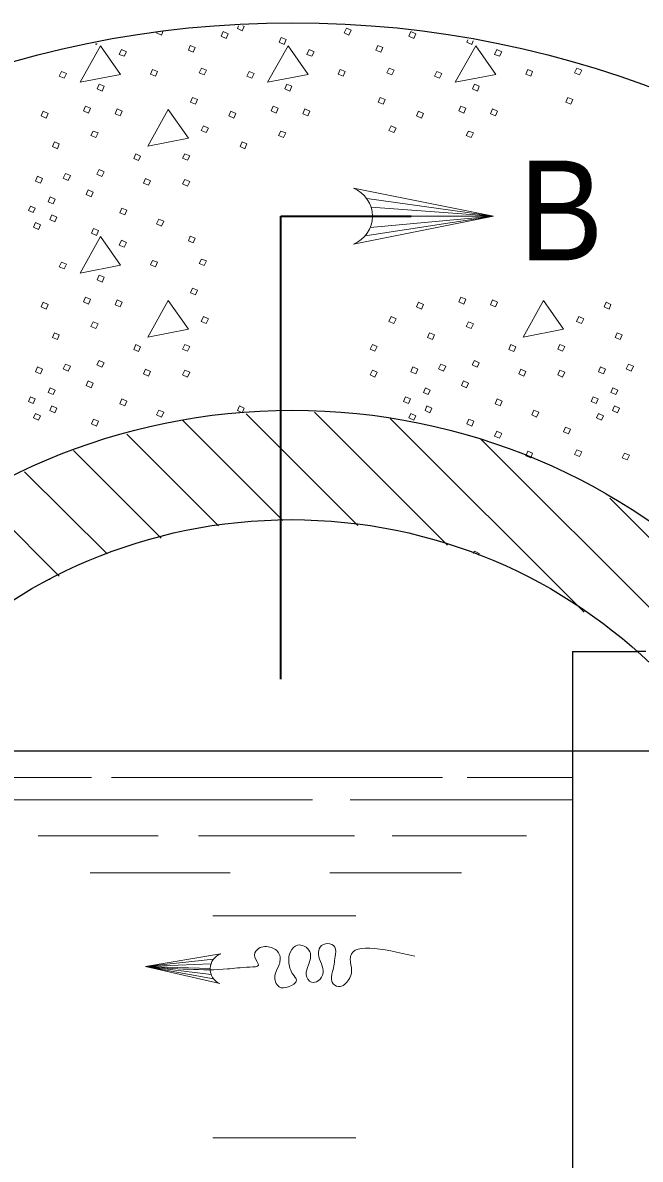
# Model space of a CAD drawing. Extents: x 1083.1 to 1117.1, y 719.4 to 741.4.
# Drawn here: x 1090.324 to 1091.808, y 735.057 to 737.789 of the extents above; entities that cross this region are included whole.
import ezdxf
from ezdxf.enums import TextEntityAlignment as Align

# ---------------------------------------------------------------- set-up
doc = ezdxf.new("R2010")
doc.units = 0
doc.header["$LTSCALE"] = 0.062
doc.linetypes.add('LONG_DASHED', pattern=[7.5, 6, -1.5])
doc.layers.add('1', color=7, linetype='Continuous', lineweight=13)

msp = doc.modelspace()

# ---------------------------------------------------------------- linework, layer by layer
at = {"layer": '1'}
for p, q in [((1091.15075, 737.36683), (1091.45517, 737.32425)), ((1091.16108, 737.34575), (1091.45517, 737.32425)), ((1091.14717, 737.27717), (1091.45517, 737.32425)), ((1091.15883, 737.29692), (1091.45517, 737.32425)), ((1091.16417, 737.32425), (1091.45517, 737.32425)), ((1090.94925, 736.59283), (1090.70783, 736.83417)), ((1091.12925, 736.58067), (1090.86067, 736.84933)), ((1091.3445, 736.53325), (1091.02483, 736.85292)), ((1091.67367, 736.372), (1091.20733, 736.83833)), ((1090.7945, 736.57975), (1090.57408, 736.80008)), ((1092.4165, 735.79717), (1091.425, 736.78842)), ((1090.65617, 736.55025), (1090.4455, 736.76075)), ((1090.52633, 736.51225), (1090.32833, 736.71008)), ((1090.4115, 736.45917), (1090.2175, 736.65317)), ((1092.27733, 736.10408), (1091.73483, 736.64642)), ((1091.40675, 736.51342), (1091.4095, 736.51883)), ((1090.38842, 736.45033), (1090.3895, 736.45317)), ((1090.3895, 736.45317), (1090.3915, 736.45217)), ((1090.24283, 735.97483), (1090.48883, 735.97483)), ((1090.53692, 735.97483), (1091.33317, 735.97483)), ((1091.39225, 735.97483), (1091.64517, 735.97483)), ((1090.28625, 735.92117), (1091.02067, 735.92117)), ((1091.11092, 735.92117), (1091.64517, 735.92117)), ((1090.36083, 735.83458), (1090.64908, 735.83458)), ((1090.74625, 735.83458), (1091.12133, 735.83458)), ((1091.21167, 735.83458), (1091.53458, 735.83458)), ((1090.48583, 735.74558), (1090.82275, 735.74558)), ((1091.06233, 735.74558), (1091.37825, 735.74558)), ((1090.781, 735.64233), (1091.12483, 735.64233)), ((1090.78225, 735.53842), (1090.619, 735.52075)), ((1090.77625, 735.52725), (1090.619, 735.52075)), ((1090.77433, 735.51583), (1090.619, 735.52075)), ((1090.77675, 735.50117), (1090.619, 735.52075)), ((1090.7825, 735.4905), (1090.619, 735.52075)), ((1090.781, 735.10858), (1091.12483, 735.10858))]:
    msp.add_line(p, q, dxfattribs=at)
at = {"layer": '1', "lineweight": 35}
for p, q in [((1090.944, 737.32425), (1091.25742, 737.32425)), ((1090.944, 736.21142), (1090.944, 737.32425))]:
    msp.add_line(p, q, dxfattribs=at)
at = {"layer": '1', "lineweight": 25}
for p, q in [((1091.64517, 736.2775), (1091.64517, 734.37467)), ((1091.64517, 736.2775), (1091.80183, 736.2775)), ((1090.24283, 736.03933), (1091.64517, 736.03933))]:
    msp.add_line(p, q, dxfattribs=at)
at = {"layer": '1', "linetype": 'LONG_DASHED', "lineweight": 25}
for p, q in [((1093.23775, 736.2775), (1091.80183, 736.2775)), ((1091.64517, 736.03933), (1095.35325, 736.03933))]:
    msp.add_line(p, q, dxfattribs=at)
at = {"layer": '1'}
for points in [[(1090.66167, 737.76967), (1090.65692, 737.75942), (1090.64508, 737.765), (1090.64592, 737.76675)], [(1090.85283, 737.78242), (1090.85633, 737.78075), (1090.85158, 737.76975), (1090.83975, 737.77525), (1090.8425, 737.78175)], [(1090.50183, 737.73933), (1090.50108, 737.73725), (1090.49825, 737.73858)], [(1091.40667, 737.74625), (1091.40317, 737.73725), (1091.39125, 737.74283), (1091.39375, 737.7485)], [(1091.11892, 737.257), (1091.45517, 737.32425), (1091.11892, 737.3915)], [(1091.4095, 736.51883), (1091.42133, 736.51325), (1091.41942, 736.5095)], [(1090.79733, 735.47925), (1090.619, 735.52075), (1090.7995, 735.55108)]]:
    msp.add_lwpolyline(points, dxfattribs=at)
for points in [[(1090.80575, 737.76817), (1090.81758, 737.76258), (1090.81283, 737.7515), (1090.801, 737.75708)], [(1091.10167, 737.77608), (1091.1135, 737.77133), (1091.108, 737.75942), (1091.09608, 737.765)], [(1091.25675, 737.76817), (1091.26858, 737.76258), (1091.26383, 737.7515), (1091.252, 737.75708)], [(1090.945, 737.75392), (1090.95683, 737.74917), (1090.95208, 737.73725), (1090.94025, 737.74283)], [(1090.51058, 737.73408), (1090.4615, 737.64625), (1090.55883, 737.66525)], [(1090.56117, 737.72542), (1090.57308, 737.71983), (1090.5675, 737.70875), (1090.55567, 737.7135)], [(1090.72658, 737.73492), (1090.73842, 737.73017), (1090.73367, 737.71908), (1090.72183, 737.72383)], [(1090.96158, 737.73408), (1090.9125, 737.64625), (1091.00983, 737.66525)], [(1091.01225, 737.72542), (1091.02408, 737.71983), (1091.01858, 737.70875), (1091.00667, 737.7135)], [(1091.17758, 737.73492), (1091.1895, 737.73017), (1091.18475, 737.71908), (1091.17283, 737.72383)], [(1091.41267, 737.73408), (1091.36358, 737.64625), (1091.46092, 737.66525)], [(1091.46325, 737.72542), (1091.47517, 737.71983), (1091.46958, 737.70875), (1091.45775, 737.7135)], [(1090.41717, 737.67242), (1090.42908, 737.66767), (1090.4235, 737.65658), (1090.41167, 737.66133)], [(1090.63558, 737.67717), (1090.64742, 737.67242), (1090.64267, 737.66133), (1090.63083, 737.66608)], [(1090.7535, 737.68033), (1090.76533, 737.67558), (1090.75983, 737.6645), (1090.74792, 737.66925)], [(1090.86825, 737.67242), (1090.88008, 737.66767), (1090.87458, 737.65658), (1090.86267, 737.66133)], [(1091.08658, 737.67717), (1091.0985, 737.67242), (1091.09375, 737.66133), (1091.08183, 737.66608)], [(1091.2045, 737.68033), (1091.21642, 737.67558), (1091.21083, 737.6645), (1091.199, 737.66925)], [(1091.31925, 737.67242), (1091.33117, 737.66767), (1091.32558, 737.65658), (1091.31375, 737.66133)], [(1091.53767, 737.67717), (1091.5495, 737.67242), (1091.54475, 737.66133), (1091.53292, 737.66608)], [(1091.65558, 737.68033), (1091.66742, 737.67558), (1091.66192, 737.6645), (1091.65, 737.66925)], [(1090.50742, 737.6415), (1090.51925, 737.63675), (1090.5145, 737.62492), (1090.50267, 737.6305)], [(1090.95842, 737.6415), (1090.97033, 737.63675), (1090.96558, 737.62492), (1090.95367, 737.6305)], [(1091.4095, 737.6415), (1091.42133, 737.63675), (1091.41658, 737.62492), (1091.40475, 737.6305)], [(1090.73208, 737.60992), (1090.744, 737.60517), (1090.73925, 737.59408), (1090.72733, 737.59883)], [(1091.18317, 737.60992), (1091.195, 737.60517), (1091.19025, 737.59408), (1091.17842, 737.59883)], [(1091.63417, 737.60992), (1091.64608, 737.60517), (1091.64133, 737.59408), (1091.62942, 737.59883)], [(1090.37292, 737.57667), (1090.38475, 737.57108), (1090.38, 737.56008), (1090.36808, 737.56558)], [(1090.47492, 737.5885), (1090.48683, 737.58375), (1090.48208, 737.57192), (1090.47017, 737.57742)], [(1090.55092, 737.58217), (1090.56275, 737.57667), (1090.558, 737.56558), (1090.54617, 737.57033)], [(1090.67358, 737.58058), (1090.6245, 737.49275), (1090.72183, 737.51175)], [(1090.82392, 737.57667), (1090.83575, 737.57108), (1090.831, 737.56008), (1090.81917, 737.56558)], [(1090.926, 737.5885), (1090.93783, 737.58375), (1090.93308, 737.57192), (1090.92125, 737.57742)], [(1091.00192, 737.58217), (1091.01383, 737.57667), (1091.00908, 737.56558), (1090.99717, 737.57033)], [(1091.27492, 737.57667), (1091.28683, 737.57108), (1091.28208, 737.56008), (1091.27017, 737.56558)], [(1091.377, 737.5885), (1091.38892, 737.58375), (1091.38417, 737.57192), (1091.37225, 737.57742)], [(1091.453, 737.58217), (1091.46483, 737.57667), (1091.46008, 737.56558), (1091.44825, 737.57033)], [(1090.49317, 737.52917), (1090.505, 737.52442), (1090.4995, 737.51333), (1090.48758, 737.51808)], [(1090.75825, 737.54183), (1090.77008, 737.53633), (1090.76458, 737.52525), (1090.75267, 737.53)], [(1090.94417, 737.52917), (1090.95608, 737.52442), (1090.9505, 737.51333), (1090.93867, 737.51808)], [(1091.20925, 737.54183), (1091.22117, 737.53633), (1091.21558, 737.52525), (1091.20375, 737.53)], [(1091.39525, 737.52917), (1091.40708, 737.52442), (1091.40158, 737.51333), (1091.38967, 737.51808)], [(1090.39975, 737.50308), (1090.41167, 737.49833), (1090.40692, 737.4865), (1090.395, 737.492)], [(1090.85083, 737.50308), (1090.86267, 737.49833), (1090.85792, 737.4865), (1090.84608, 737.492)], [(1090.59525, 737.47458), (1090.60708, 737.46908), (1090.60233, 737.458), (1090.5905, 737.46275)], [(1090.71317, 737.47458), (1090.725, 737.46983), (1090.7195, 737.45875), (1090.70758, 737.4635)], [(1090.50742, 737.43658), (1090.51925, 737.43108), (1090.51375, 737.42), (1090.50183, 737.4255)], [(1090.35942, 737.42075), (1090.37125, 737.41525), (1090.36658, 737.40417), (1090.35467, 737.40892)], [(1090.42667, 737.42708), (1090.43858, 737.42233), (1090.433, 737.4105), (1090.42117, 737.41608)], [(1090.619, 737.41525), (1090.63083, 737.40975), (1090.62608, 737.39867), (1090.61425, 737.40417)], [(1090.71317, 737.41292), (1090.725, 737.40817), (1090.7195, 737.39625), (1090.70758, 737.40183)], [(1090.48125, 737.38758), (1090.49317, 737.382), (1090.48842, 737.37092), (1090.4765, 737.3765)], [(1090.3895, 737.37092), (1090.40133, 737.36542), (1090.39658, 737.35433), (1090.38475, 737.35908)], [(1090.342, 737.34875), (1090.35392, 737.344), (1090.34917, 737.333), (1090.33725, 737.33775)], [(1090.39342, 737.32742), (1090.40533, 737.32192), (1090.40058, 737.31083), (1090.38867, 737.31633)], [(1090.562, 737.344), (1090.57383, 737.3385), (1090.56908, 737.32742), (1090.55725, 737.33217)], [(1090.35467, 737.30925), (1090.36658, 737.30367), (1090.36183, 737.29258), (1090.34992, 737.29817)], [(1090.65058, 737.31717), (1090.6625, 737.31242), (1090.65692, 737.3005), (1090.64508, 737.30608)], [(1090.51058, 737.27517), (1090.4615, 737.18742), (1090.55883, 737.20633)], [(1090.49392, 737.295), (1090.50583, 737.29025), (1090.50108, 737.27833), (1090.48917, 737.28392)], [(1090.72658, 737.276), (1090.73842, 737.27125), (1090.73367, 737.26017), (1090.72183, 737.26492)], [(1090.56117, 737.2665), (1090.57308, 737.261), (1090.5675, 737.24992), (1090.55567, 737.25467)], [(1090.63558, 737.21825), (1090.64742, 737.2135), (1090.64267, 737.20242), (1090.63083, 737.20717)], [(1090.7535, 737.22142), (1090.76533, 737.21667), (1090.75983, 737.20558), (1090.74792, 737.21033)], [(1090.41717, 737.2135), (1090.42908, 737.20875), (1090.4235, 737.19767), (1090.41167, 737.20242)], [(1090.50742, 737.18267), (1090.51925, 737.17792), (1090.5145, 737.166), (1090.50267, 737.17158)], [(1090.73208, 737.151), (1090.744, 737.14625), (1090.73925, 737.13517), (1090.72733, 737.13992)], [(1090.37292, 737.11775), (1090.38475, 737.11225), (1090.38, 737.10117), (1090.36808, 737.10667)], [(1090.47492, 737.12958), (1090.48683, 737.12492), (1090.48208, 737.113), (1090.47017, 737.11858)], [(1090.55092, 737.12333), (1090.56275, 737.11775), (1090.558, 737.10667), (1090.54617, 737.11142)], [(1090.67358, 737.12175), (1090.6245, 737.03392), (1090.72183, 737.05283)], [(1091.27492, 737.11775), (1091.28683, 737.11225), (1091.28208, 737.10117), (1091.27017, 737.10667)], [(1091.377, 737.12958), (1091.38892, 737.12492), (1091.38417, 737.113), (1091.37225, 737.11858)], [(1091.453, 737.12333), (1091.46483, 737.11775), (1091.46008, 737.10667), (1091.44825, 737.11142)], [(1091.57567, 737.12175), (1091.52658, 737.03392), (1091.62392, 737.05283)], [(1091.726, 737.11775), (1091.73783, 737.11225), (1091.73308, 737.10117), (1091.72125, 737.10667)], [(1090.75825, 737.08292), (1090.77008, 737.07742), (1090.76458, 737.06633), (1090.75267, 737.07108)], [(1091.20925, 737.08292), (1091.22117, 737.07742), (1091.21558, 737.06633), (1091.20375, 737.07108)], [(1091.66033, 737.08292), (1091.67217, 737.07742), (1091.66667, 737.06633), (1091.65475, 737.07108)], [(1090.49317, 737.07025), (1090.505, 737.0655), (1090.4995, 737.05442), (1090.48758, 737.05917)], [(1091.39525, 737.07025), (1091.40708, 737.0655), (1091.40158, 737.05442), (1091.38967, 737.05917)], [(1090.39975, 737.04417), (1090.41167, 737.03942), (1090.40692, 737.02758), (1090.395, 737.03308)], [(1091.30183, 737.04417), (1091.31375, 737.03942), (1091.309, 737.02758), (1091.29708, 737.03308)], [(1091.75292, 737.04417), (1091.76475, 737.03942), (1091.76, 737.02758), (1091.74817, 737.03308)], [(1090.59525, 737.01567), (1090.60708, 737.01017), (1090.60233, 736.99908), (1090.5905, 737.00383)], [(1090.71317, 737.01567), (1090.725, 737.01092), (1090.7195, 736.99983), (1090.70758, 737.00458)], [(1091.16417, 737.01567), (1091.176, 737.01092), (1091.1705, 736.99983), (1091.15867, 737.00458)], [(1091.49733, 737.01567), (1091.50917, 737.01017), (1091.50442, 736.99908), (1091.49258, 737.00383)], [(1091.61517, 737.01567), (1091.62708, 737.01092), (1091.6215, 736.99983), (1091.60967, 737.00458)], [(1090.50742, 736.97775), (1090.51925, 736.97217), (1090.51375, 736.96108), (1090.50183, 736.96667)], [(1091.4095, 736.97775), (1091.42133, 736.97217), (1091.41583, 736.96108), (1091.40392, 736.96667)], [(1090.35942, 736.96192), (1090.37125, 736.95633), (1090.36658, 736.94525), (1090.35467, 736.95)], [(1090.42667, 736.96825), (1090.43858, 736.9635), (1090.433, 736.95158), (1090.42117, 736.95717)], [(1090.619, 736.95633), (1090.63083, 736.95083), (1090.62608, 736.93975), (1090.61425, 736.94525)], [(1090.71317, 736.954), (1090.725, 736.94925), (1090.7195, 736.93733), (1090.70758, 736.94292)], [(1091.16417, 736.954), (1091.176, 736.94925), (1091.1705, 736.93733), (1091.15867, 736.94292)], [(1091.2615, 736.96192), (1091.27333, 736.95633), (1091.26858, 736.94525), (1091.25675, 736.95)], [(1091.32875, 736.96825), (1091.34067, 736.9635), (1091.33508, 736.95158), (1091.32325, 736.95717)], [(1091.521, 736.95633), (1091.53292, 736.95083), (1091.52817, 736.93975), (1091.51633, 736.94525)], [(1091.61517, 736.954), (1091.62708, 736.94925), (1091.6215, 736.93733), (1091.60967, 736.94292)], [(1091.7125, 736.96192), (1091.72442, 736.95633), (1091.71967, 736.94525), (1091.70775, 736.95)], [(1091.77983, 736.96825), (1091.79167, 736.9635), (1091.78608, 736.95158), (1091.77425, 736.95717)], [(1090.48125, 736.92867), (1090.49317, 736.92308), (1090.48842, 736.91208), (1090.4765, 736.91758)], [(1091.38333, 736.92867), (1091.39525, 736.92308), (1091.3905, 736.91208), (1091.37858, 736.91758)], [(1090.342, 736.88992), (1090.35392, 736.88517), (1090.34917, 736.87408), (1090.33725, 736.87883)], [(1090.3895, 736.91208), (1090.40133, 736.9065), (1090.39658, 736.89542), (1090.38475, 736.90017)], [(1091.24408, 736.88992), (1091.25592, 736.88517), (1091.25125, 736.87408), (1091.23933, 736.87883)], [(1091.29158, 736.91208), (1091.30342, 736.9065), (1091.29867, 736.89542), (1091.28683, 736.90017)], [(1091.69517, 736.88992), (1091.707, 736.88517), (1091.70225, 736.87408), (1091.69042, 736.87883)], [(1091.74258, 736.91208), (1091.7545, 736.9065), (1091.74975, 736.89542), (1091.73783, 736.90017)], [(1090.39342, 736.8685), (1090.40533, 736.863), (1090.40058, 736.85192), (1090.38867, 736.85742)], [(1090.562, 736.88517), (1090.57383, 736.87958), (1090.56908, 736.8685), (1090.55725, 736.87325)], [(1090.8445, 736.8685), (1090.85633, 736.863), (1090.85158, 736.85192), (1090.83975, 736.85742)], [(1091.2955, 736.8685), (1091.30742, 736.863), (1091.30267, 736.85192), (1091.29075, 736.85742)], [(1091.46408, 736.88517), (1091.47592, 736.87958), (1091.47117, 736.8685), (1091.45933, 736.87325)], [(1091.74658, 736.8685), (1091.75842, 736.863), (1091.75367, 736.85192), (1091.74183, 736.85742)], [(1090.35467, 736.85033), (1090.36658, 736.84475), (1090.36183, 736.83375), (1090.34992, 736.83925)], [(1090.49392, 736.83608), (1090.50583, 736.83133), (1090.50108, 736.8195), (1090.48917, 736.825)], [(1090.65058, 736.85825), (1090.6625, 736.8535), (1090.65692, 736.84158), (1090.64508, 736.84717)], [(1091.25675, 736.85033), (1091.26858, 736.84475), (1091.26383, 736.83375), (1091.252, 736.83925)], [(1091.396, 736.83608), (1091.40792, 736.83133), (1091.40317, 736.8195), (1091.39125, 736.825)], [(1091.55267, 736.85825), (1091.56458, 736.8535), (1091.559, 736.84158), (1091.54717, 736.84717)], [(1091.70775, 736.85033), (1091.71967, 736.84475), (1091.71492, 736.83375), (1091.703, 736.83925)], [(1091.46325, 736.80758), (1091.47517, 736.80208), (1091.46958, 736.791), (1091.45775, 736.79575)], [(1091.62867, 736.81708), (1091.6405, 736.81233), (1091.63575, 736.80125), (1091.62392, 736.806)], [(1091.53767, 736.75933), (1091.5495, 736.75458), (1091.54475, 736.7435), (1091.53292, 736.74825)], [(1091.65558, 736.7625), (1091.66742, 736.75775), (1091.66192, 736.74667), (1091.65, 736.75142)], [(1091.77033, 736.75458), (1091.78217, 736.74983), (1091.77667, 736.73875), (1091.76475, 736.7435)]]:
    msp.add_lwpolyline(points, close=True, dxfattribs=at)
msp.add_arc((1091.09174, 737.32434), 0.07258, 292.08605, 67.91218, dxfattribs=at)
at = {"layer": '1', "lineweight": 25}
for centre, major_axis in [((1090.97275, 735.33737), (2.45238, 0)), ((1090.9718, 735.34212), (1.5159, 0)), ((1090.96895, 735.34307), (1.25185, 0))]:
    msp.add_ellipse(centre, major_axis=major_axis, ratio=0.999895, dxfattribs=at)
at = {"layer": '1'}
msp.add_ellipse((1090.81299, 735.51469), major_axis=(-0.03875, 0), ratio=0.999895, start_param=5.0665441, end_param=7.4371572, dxfattribs=at)
msp.add_spline([(1091.26633, 735.54525), (1091.11108, 735.5365), (1091.11408, 735.505), (1091.10783, 735.48925), (1091.08292, 735.47242), (1091.0675, 735.48267), (1091.06858, 735.5085), (1091.07492, 735.54442), (1091.07392, 735.567), (1091.05642, 735.576), (1091.03883, 735.56708), (1091.03458, 735.55017), (1091.04167, 735.52658), (1091.04575, 735.50517), (1091.03425, 735.486), (1091.01767, 735.48275), (1091.00533, 735.50075), (1091.01067, 735.52433), (1091.01392, 735.55583), (1091.0005, 735.56933), (1090.984, 735.57167), (1090.96733, 735.55592), (1090.96308, 735.53233), (1090.97333, 735.50183), (1090.9815, 735.48725), (1090.96275, 735.47158), (1090.94008, 735.47158), (1090.92975, 735.49867), (1090.93917, 735.52225), (1090.94042, 735.55033), (1090.91775, 735.56725), (1090.88767, 735.56167), (1090.88133, 735.54258), (1090.8905, 735.5235), (1090.86983, 735.519), (1090.81608, 735.51458), (1090.619, 735.52075)], degree=3, dxfattribs=at)

# ---------------------------------------------------------------- texts
at = {"layer": '1', "width": 0.95}
msp.add_text('B', height=0.24, dxfattribs=at).set_placement((1091.61817, 737.21825), align=Align.CENTER)

doc.saveas('drawing.dxf')
